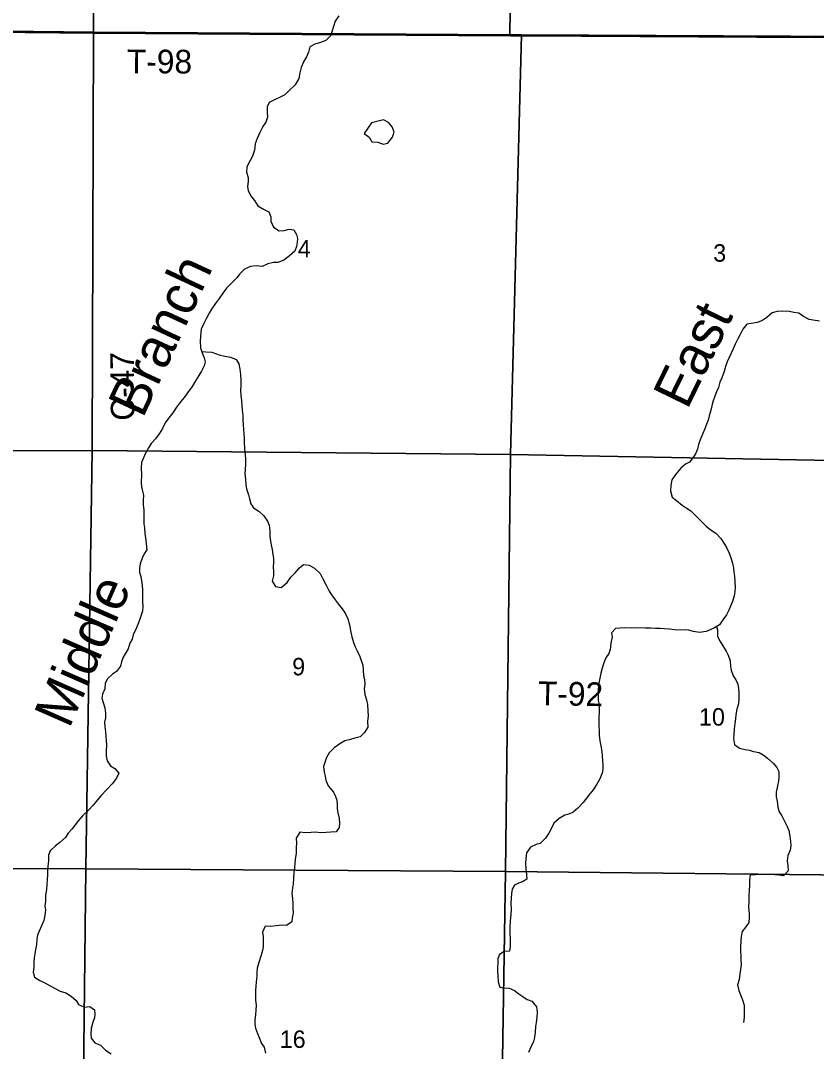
# Model space of a CAD drawing. Extents: x 1772825 to 1773716, y 1138558 to 1139032.
# Drawn here: x 1772825.891 to 1772826.846, y 1138559.911 to 1138561.147 of the extents above; entities that cross this region are included whole.
import ezdxf

# ---------------------------------------------------------------- set-up
doc = ezdxf.new("R2010")
doc.units = 0
for name, color, linetype in [('GM_X_County_Road_Text', 7, 'Continuous'), ('GM_X_Minor_Lake', 7, 'Continuous'), ('GM_X_Minor_River', 7, 'Continuous'), ('GM_X_Minor_River_Text', 7, 'Continuous'), ('GM_X_Section', 7, 'Continuous'), ('GM_X_Section_Text', 7, 'Continuous'), ('GM_X_Township', 7, 'Continuous'), ('GM_X_Township_Road_Text', 7, 'Continuous')]:
    doc.layers.add(name, color=color, linetype=linetype)

msp = doc.modelspace()

# ---------------------------------------------------------------- linework, layer by layer
at = {"layer": 'GM_X_Minor_Lake'}
for points in [[(1772826.3344, 1138561.0034), (1772826.3373, 1138561.0073), (1772826.3393, 1138561.0134), (1772826.3369, 1138561.0198), (1772826.3325, 1138561.0248), (1772826.3265, 1138561.028), (1772826.3121, 1138561.0244), (1772826.3036, 1138561.0115)], [(1772826.3036, 1138561.0115), (1772826.3095, 1138561.0073), (1772826.3127, 1138561.0018), (1772826.3199, 1138561.0014), (1772826.3261, 1138560.9988), (1772826.332, 1138561.0001), (1772826.3344, 1138561.0034)]]:
    msp.add_lwpolyline(points, dxfattribs=at)
at = {"layer": 'GM_X_Minor_River'}
for points in [[(1772826.273, 1138561.1527), (1772826.2686, 1138561.1465), (1772826.2667, 1138561.1398), (1772826.2646, 1138561.1337), (1772826.2629, 1138561.1286), (1772826.2576, 1138561.1231), (1772826.2512, 1138561.1209), (1772826.2444, 1138561.1188), (1772826.2384, 1138561.1157), (1772826.2365, 1138561.1093), (1772826.2342, 1138561.1034), (1772826.2308, 1138561.0977), (1772826.228, 1138561.0907), (1772826.2264, 1138561.0844), (1772826.2249, 1138561.0776), (1772826.2206, 1138561.0702), (1772826.214, 1138561.0638), (1772826.2081, 1138561.0581), (1772826.2028, 1138561.0551), (1772826.196, 1138561.052), (1772826.1894, 1138561.0488), (1772826.1871, 1138561.0437), (1772826.1871, 1138561.0374), (1772826.1875, 1138561.0313), (1772826.1854, 1138561.0251), (1772826.182, 1138561.02), (1772826.1784, 1138561.0128), (1772826.175, 1138561.0057), (1772826.1725, 1138560.9993), (1772826.1718, 1138560.9915), (1772826.1693, 1138560.9843), (1772826.1667, 1138560.9794), (1772826.1625, 1138560.9718), (1772826.1623, 1138560.9652), (1772826.1644, 1138560.9587), (1772826.1644, 1138560.954), (1772826.1635, 1138560.9479), (1772826.1644, 1138560.9428), (1772826.1682, 1138560.9358), (1772826.1718, 1138560.9311), (1772826.176, 1138560.925), (1772826.1826, 1138560.9208), (1772826.189, 1138560.9176), (1772826.1913, 1138560.9115), (1772826.1915, 1138560.9064), (1772826.1945, 1138560.8994), (1772826.2013, 1138560.895), (1772826.2075, 1138560.8951), (1772826.2136, 1138560.8968), (1772826.2189, 1138560.8962), (1772826.2223, 1138560.8903), (1772826.2234, 1138560.8856), (1772826.2232, 1138560.8808), (1772826.2223, 1138560.8761), (1772826.2202, 1138560.8706), (1772826.2138, 1138560.8651), (1772826.207, 1138560.8596), (1772826.2, 1138560.8568), (1772826.1945, 1138560.8568), (1772826.1879, 1138560.8554), (1772826.1812, 1138560.852), (1772826.1739, 1138560.8528), (1772826.1671, 1138560.852), (1772826.1597, 1138560.8488), (1772826.154, 1138560.8431), (1772826.1508, 1138560.8384), (1772826.1442, 1138560.8321), (1772826.1383, 1138560.8262), (1772826.134, 1138560.8203), (1772826.1296, 1138560.8137), (1772826.1249, 1138560.8073), (1772826.1205, 1138560.801), (1772826.1177, 1138560.7963), (1772826.1143, 1138560.79), (1772826.1113, 1138560.7839), (1772826.1081, 1138560.7771)], [(1772826.8497, 1138560.7867), (1772826.8418, 1138560.7877), (1772826.8371, 1138560.7885), (1772826.8302, 1138560.792), (1772826.8248, 1138560.796), (1772826.8189, 1138560.797), (1772826.8136, 1138560.798), (1772826.8047, 1138560.7984), (1772826.799, 1138560.7981), (1772826.7927, 1138560.7964), (1772826.7866, 1138560.7908), (1772826.7805, 1138560.787), (1772826.775, 1138560.785), (1772826.7676, 1138560.7839), (1772826.7626, 1138560.7828), (1772826.7578, 1138560.777), (1772826.7544, 1138560.7705), (1772826.7515, 1138560.7653), (1772826.7484, 1138560.7588), (1772826.7459, 1138560.7532), (1772826.7436, 1138560.7482), (1772826.7413, 1138560.7431), (1772826.739, 1138560.7378), (1772826.737, 1138560.732), (1772826.7353, 1138560.7263), (1772826.7324, 1138560.7184), (1772826.7302, 1138560.7134), (1772826.7283, 1138560.707), (1772826.726, 1138560.7019), (1772826.724, 1138560.6964), (1772826.7219, 1138560.6909), (1772826.7205, 1138560.6851), (1772826.7192, 1138560.6796), (1772826.7174, 1138560.6731), (1772826.7159, 1138560.6678), (1772826.7141, 1138560.6629), (1772826.712, 1138560.6572), (1772826.7091, 1138560.6508), (1772826.7064, 1138560.6442), (1772826.7046, 1138560.6387), (1772826.7033, 1138560.6332), (1772826.7008, 1138560.6274), (1772826.6975, 1138560.6225), (1772826.6937, 1138560.6176), (1772826.6889, 1138560.6149), (1772826.6832, 1138560.6102)], [(1772826.1081, 1138560.7771), (1772826.1071, 1138560.7684), (1772826.1069, 1138560.7625), (1772826.1073, 1138560.7547), (1772826.1094, 1138560.7472), (1772826.1115, 1138560.7424), (1772826.1126, 1138560.7377), (1772826.1115, 1138560.7328), (1772826.1084, 1138560.7267), (1772826.105, 1138560.7214), (1772826.1012, 1138560.7149), (1772826.0971, 1138560.7083), (1772826.0916, 1138560.7007), (1772826.0874, 1138560.6948), (1772826.0831, 1138560.6897), (1772826.0784, 1138560.6833), (1772826.074, 1138560.6764), (1772826.0691, 1138560.6706), (1772826.0647, 1138560.6645), (1772826.0615, 1138560.6579), (1772826.0577, 1138560.6512), (1772826.0532, 1138560.6452), (1772826.0479, 1138560.6399), (1772826.0447, 1138560.6347), (1772826.0411, 1138560.6281), (1772826.0386, 1138560.6228), (1772826.0364, 1138560.6169), (1772826.036, 1138560.6101), (1772826.0362, 1138560.6027), (1772826.0358, 1138560.5932), (1772826.0364, 1138560.5879), (1772826.0377, 1138560.5828), (1772826.0386, 1138560.5777), (1772826.0384, 1138560.5714), (1772826.0384, 1138560.5663), (1772826.039, 1138560.5602), (1772826.0392, 1138560.5546), (1772826.0392, 1138560.5485), (1772826.039, 1138560.5436), (1772826.0398, 1138560.5385), (1772826.0405, 1138560.5318), (1772826.0411, 1138560.5265), (1772826.0418, 1138560.5195), (1772826.0428, 1138560.5123), (1772826.0396, 1138560.5074), (1772826.0371, 1138560.5021), (1772826.0348, 1138560.4954), (1772826.0341, 1138560.4901), (1772826.0341, 1138560.4852), (1772826.0354, 1138560.4801), (1772826.0367, 1138560.4727), (1772826.0377, 1138560.4651), (1772826.0375, 1138560.4598), (1772826.0375, 1138560.4549), (1772826.0377, 1138560.4496), (1772826.0379, 1138560.4444), (1772826.0375, 1138560.4386), (1772826.035, 1138560.4314), (1772826.0329, 1138560.4245), (1772826.0299, 1138560.4177), (1772826.0263, 1138560.4101), (1772826.025, 1138560.4052), (1772826.0225, 1138560.4005), (1772826.0203, 1138560.3936), (1772826.0167, 1138560.3876), (1772826.014, 1138560.3826), (1772826.0123, 1138560.3779), (1772826.011, 1138560.3728), (1772826.0065, 1138560.3663), (1772826.0014, 1138560.3631), (1772825.9957, 1138560.3576), (1772825.9927, 1138560.3523), (1772825.9923, 1138560.3457), (1772825.9894, 1138560.3392), (1772825.9887, 1138560.3345), (1772825.9904, 1138560.3292), (1772825.9923, 1138560.3229), (1772825.993, 1138560.3165), (1772825.993, 1138560.3106), (1772825.9921, 1138560.3055), (1772825.9925, 1138560.3004), (1772825.9932, 1138560.2939), (1772825.9936, 1138560.2886), (1772825.9938, 1138560.2831), (1772825.9943, 1138560.278), (1772825.994, 1138560.2714), (1772825.9938, 1138560.2653), (1772825.9953, 1138560.259), (1772825.9991, 1138560.2532), (1772826.0042, 1138560.2499), (1772826.0091, 1138560.2445), (1772826.0064, 1138560.2384), (1772826.0012, 1138560.2317), (1772825.9942, 1138560.2242), (1772825.9881, 1138560.2175), (1772825.9834, 1138560.2124), (1772825.9785, 1138560.2058), (1772825.9726, 1138560.2001), (1772825.9656, 1138560.1933), (1772825.9607, 1138560.1874), (1772825.9569, 1138560.1823)], [(1772826.1086, 1138560.7501), (1772826.1135, 1138560.7498), (1772826.1209, 1138560.7494), (1772826.1296, 1138560.746), (1772826.1362, 1138560.7447), (1772826.1432, 1138560.7432), (1772826.1497, 1138560.7407), (1772826.1532, 1138560.7352), (1772826.1542, 1138560.729), (1772826.1551, 1138560.7225), (1772826.1555, 1138560.7159), (1772826.1555, 1138560.7091), (1772826.1551, 1138560.7038), (1772826.1555, 1138560.6973), (1772826.1563, 1138560.6913), (1772826.1566, 1138560.6856), (1772826.157, 1138560.6799), (1772826.1578, 1138560.6734), (1772826.158, 1138560.6681), (1772826.1583, 1138560.6621), (1772826.1587, 1138560.6566), (1772826.1589, 1138560.6516), (1772826.1593, 1138560.6463), (1772826.1595, 1138560.6412), (1772826.16, 1138560.6335), (1772826.1608, 1138560.6264), (1772826.161, 1138560.6209), (1772826.161, 1138560.6151), (1772826.1606, 1138560.6084), (1772826.1604, 1138560.6037), (1772826.161, 1138560.5967), (1772826.1616, 1138560.5906), (1772826.1623, 1138560.5853), (1772826.1646, 1138560.5781), (1772826.1657, 1138560.5734), (1772826.1676, 1138560.5673), (1772826.1706, 1138560.5626), (1772826.1771, 1138560.5588), (1772826.1831, 1138560.5529), (1772826.1876, 1138560.5468), (1772826.1895, 1138560.5417), (1772826.1901, 1138560.5353), (1772826.1901, 1138560.5286), (1772826.191, 1138560.5226), (1772826.192, 1138560.5177), (1772826.1929, 1138560.5127), (1772826.1939, 1138560.5068), (1772826.1948, 1138560.5021), (1772826.1948, 1138560.4974), (1772826.1944, 1138560.4915), (1772826.1948, 1138560.4868), (1772826.1946, 1138560.4809), (1772826.1931, 1138560.4748), (1772826.1971, 1138560.4684), (1772826.2037, 1138560.4672), (1772826.2109, 1138560.4729), (1772826.2156, 1138560.4794), (1772826.2205, 1138560.4845), (1772826.2258, 1138560.4906), (1772826.2308, 1138560.4947), (1772826.2376, 1138560.494), (1772826.2438, 1138560.4904), (1772826.2506, 1138560.4837), (1772826.2538, 1138560.4775), (1772826.2576, 1138560.4705), (1772826.2612, 1138560.4635), (1772826.2642, 1138560.4584), (1772826.2686, 1138560.4521), (1772826.2722, 1138560.4474), (1772826.2769, 1138560.4415), (1772826.2805, 1138560.4364), (1772826.2837, 1138560.4294), (1772826.286, 1138560.4223), (1772826.2871, 1138560.4155), (1772826.2886, 1138560.4079), (1772826.2907, 1138560.4011), (1772826.2926, 1138560.396), (1772826.2949, 1138560.3911), (1772826.2983, 1138560.3844), (1772826.302, 1138560.3738), (1772826.3022, 1138560.3681), (1772826.3028, 1138560.3613), (1772826.3037, 1138560.3566), (1772826.3041, 1138560.3511), (1772826.3035, 1138560.3454), (1772826.3041, 1138560.3388), (1772826.3062, 1138560.3325), (1772826.3073, 1138560.3268), (1772826.3079, 1138560.3192), (1772826.3083, 1138560.313), (1772826.3075, 1138560.3064), (1772826.3077, 1138560.2997), (1772826.3039, 1138560.2933), (1772826.2986, 1138560.2878), (1772826.2922, 1138560.2863), (1772826.2871, 1138560.2849), (1772826.2801, 1138560.283), (1772826.2742, 1138560.2796), (1772826.2676, 1138560.2749), (1772826.2616, 1138560.2688), (1772826.2583, 1138560.2631)], [(1772826.6832, 1138560.6102), (1772826.6772, 1138560.6031), (1772826.6726, 1138560.5963), (1772826.6711, 1138560.5896), (1772826.6708, 1138560.583), (1772826.6729, 1138560.5756), (1772826.678, 1138560.5714), (1772826.6849, 1138560.566), (1772826.6898, 1138560.5626), (1772826.6951, 1138560.5589), (1772826.7, 1138560.5543), (1772826.7074, 1138560.5471), (1772826.7136, 1138560.5408), (1772826.7185, 1138560.5368), (1772826.7253, 1138560.5323), (1772826.7311, 1138560.5258), (1772826.7358, 1138560.519), (1772826.7384, 1138560.5142), (1772826.7412, 1138560.5081), (1772826.7436, 1138560.5015), (1772826.7453, 1138560.4963), (1772826.7466, 1138560.4908), (1772826.7469, 1138560.4853), (1772826.7477, 1138560.4806), (1772826.7482, 1138560.4734), (1772826.7485, 1138560.4675), (1772826.7481, 1138560.4618), (1772826.7471, 1138560.4569), (1772826.7453, 1138560.4501), (1772826.743, 1138560.4448), (1772826.7407, 1138560.4399), (1772826.738, 1138560.4344), (1772826.7338, 1138560.4281), (1772826.7296, 1138560.4223), (1772826.7237, 1138560.4187), (1772826.7185, 1138560.4163), (1772826.7136, 1138560.4141), (1772826.7058, 1138560.4132), (1772826.6986, 1138560.4144), (1772826.6923, 1138560.4159), (1772826.6876, 1138560.4162), (1772826.6827, 1138560.416), (1772826.6756, 1138560.4163), (1772826.6696, 1138560.4171), (1772826.6635, 1138560.4173), (1772826.6584, 1138560.4177), (1772826.6527, 1138560.4179), (1772826.6474, 1138560.4182), (1772826.6408, 1138560.4184), (1772826.629, 1138560.4185), (1772826.6239, 1138560.4183), (1772826.6159, 1138560.4186), (1772826.6104, 1138560.4181), (1772826.6049, 1138560.4179), (1772826.6001, 1138560.4128), (1772826.601, 1138560.4077), (1772826.5993, 1138560.4005), (1772826.5986, 1138560.3927), (1772826.5969, 1138560.3878), (1772826.5934, 1138560.3827), (1772826.5909, 1138560.3769), (1772826.5888, 1138560.3702), (1772826.5872, 1138560.3642), (1772826.586, 1138560.3583), (1772826.585, 1138560.3524), (1772826.584, 1138560.3447), (1772826.584, 1138560.3386), (1772826.5841, 1138560.332), (1772826.5852, 1138560.3255), (1772826.5854, 1138560.3175), (1772826.5851, 1138560.3111), (1772826.5849, 1138560.3063), (1772826.585, 1138560.3008), (1772826.5852, 1138560.2953), (1772826.5853, 1138560.2898), (1772826.5861, 1138560.2832), (1772826.5879, 1138560.2752), (1772826.5884, 1138560.2699), (1772826.589, 1138560.2652), (1772826.5893, 1138560.2595), (1772826.5898, 1138560.254), (1772826.5898, 1138560.2492), (1772826.5888, 1138560.2443), (1772826.5857, 1138560.2367), (1772826.5824, 1138560.2311), (1772826.5782, 1138560.2245), (1772826.5742, 1138560.2195), (1772826.57, 1138560.2143), (1772826.5663, 1138560.2092), (1772826.5598, 1138560.2022), (1772826.5541, 1138560.1977), (1772826.549, 1138560.1953), (1772826.544, 1138560.1938), (1772826.5375, 1138560.19), (1772826.5309, 1138560.1844), (1772826.5278, 1138560.1774), (1772826.5251, 1138560.1725), (1772826.5211, 1138560.1663), (1772826.5146, 1138560.1601), (1772826.5096, 1138560.159), (1772826.5028, 1138560.1556)], [(1772826.7261, 1138560.4202), (1772826.7273, 1138560.4157), (1772826.7272, 1138560.4081), (1772826.7306, 1138560.4024), (1772826.7338, 1138560.3972), (1772826.7375, 1138560.3907), (1772826.7399, 1138560.386), (1772826.7423, 1138560.379), (1772826.7429, 1138560.3727), (1772826.7436, 1138560.3678), (1772826.7462, 1138560.3613), (1772826.7494, 1138560.3563), (1772826.7518, 1138560.3512), (1772826.7525, 1138560.3461), (1772826.7527, 1138560.3409), (1772826.7528, 1138560.3345), (1772826.7524, 1138560.3277), (1772826.7506, 1138560.321), (1772826.7491, 1138560.3144), (1772826.7487, 1138560.3097), (1772826.7479, 1138560.304), (1772826.7472, 1138560.2974), (1772826.7468, 1138560.2909), (1772826.7464, 1138560.286), (1772826.7477, 1138560.2789), (1772826.7535, 1138560.2742), (1772826.7603, 1138560.2728), (1772826.7655, 1138560.2718), (1772826.7706, 1138560.2702), (1772826.7772, 1138560.2691), (1772826.7821, 1138560.2664), (1772826.7872, 1138560.2625), (1772826.7942, 1138560.2564), (1772826.7983, 1138560.2511), (1772826.8007, 1138560.2463), (1772826.8007, 1138560.2399), (1772826.8003, 1138560.2347), (1772826.7991, 1138560.2291), (1772826.7977, 1138560.2217), (1772826.7977, 1138560.216), (1772826.7988, 1138560.2108), (1772826.7997, 1138560.2034), (1772826.8011, 1138560.1981), (1772826.8045, 1138560.1932), (1772826.8075, 1138560.1869), (1772826.8107, 1138560.1802), (1772826.8129, 1138560.1755), (1772826.8142, 1138560.1688), (1772826.8149, 1138560.1625), (1772826.8151, 1138560.1578), (1772826.8143, 1138560.1521), (1772826.8118, 1138560.1457), (1772826.811, 1138560.1392), (1772826.8117, 1138560.1335), (1772826.8122, 1138560.1273), (1772826.8066, 1138560.1214), (1772826.801, 1138560.1221), (1772826.796, 1138560.1225), (1772826.79, 1138560.1227), (1772826.7837, 1138560.1228), (1772826.7786, 1138560.1228), (1772826.7729, 1138560.1226), (1772826.7664, 1138560.1225), (1772826.7658, 1138560.1161), (1772826.7658, 1138560.1094), (1772826.7652, 1138560.1039), (1772826.7649, 1138560.0975), (1772826.7649, 1138560.0906), (1772826.7646, 1138560.0838), (1772826.7651, 1138560.076), (1772826.7653, 1138560.0711), (1772826.7649, 1138560.0654), (1772826.7614, 1138560.0601), (1772826.7568, 1138560.0543), (1772826.7556, 1138560.0484), (1772826.7552, 1138560.0433), (1772826.7548, 1138560.0357), (1772826.7548, 1138560.0306), (1772826.7551, 1138560.0258), (1772826.7552, 1138560.0207), (1772826.7556, 1138560.0148), (1772826.755, 1138560.0088), (1772826.7542, 1138560.0038), (1772826.7532, 1138559.997), (1772826.7514, 1138559.9904), (1772826.7527, 1138559.9835), (1772826.7549, 1138559.9786), (1772826.7574, 1138559.9723), (1772826.7592, 1138559.9659), (1772826.7592, 1138559.9586), (1772826.7591, 1138559.9514), (1772826.7583, 1138559.9454)], [(1772826.2583, 1138560.2631), (1772826.2561, 1138560.2572), (1772826.2546, 1138560.2523), (1772826.2553, 1138560.2457), (1772826.2565, 1138560.2407), (1772826.2576, 1138560.2358), (1772826.2604, 1138560.2292), (1772826.2667, 1138560.2216), (1772826.2691, 1138560.2165), (1772826.2706, 1138560.2118), (1772826.2712, 1138560.2068), (1772826.271, 1138560.2019), (1772826.2718, 1138560.1968), (1772826.2735, 1138560.1901), (1772826.274, 1138560.1843), (1772826.2735, 1138560.1793), (1772826.2699, 1138560.174), (1772826.2633, 1138560.1735), (1772826.2578, 1138560.1731), (1772826.251, 1138560.1729), (1772826.2449, 1138560.1735), (1772826.24, 1138560.1731), (1772826.2332, 1138560.1729), (1772826.2264, 1138560.1734), (1772826.2218, 1138560.1666), (1772826.2222, 1138560.1606), (1772826.222, 1138560.1554), (1772826.2217, 1138560.1484), (1772826.2205, 1138560.141), (1772826.2201, 1138560.1363), (1772826.2198, 1138560.131), (1772826.219, 1138560.1255), (1772826.2186, 1138560.1181), (1772826.2181, 1138560.1116), (1772826.2175, 1138560.1069), (1772826.2167, 1138560.1005), (1772826.2175, 1138560.0936), (1772826.2179, 1138560.0889), (1772826.2179, 1138560.0824), (1772826.2181, 1138560.0766), (1772826.2171, 1138560.0709), (1772826.2167, 1138560.066), (1772826.2101, 1138560.0616), (1772826.2052, 1138560.062), (1772826.1978, 1138560.0614), (1772826.1912, 1138560.0604), (1772826.1846, 1138560.061), (1772826.1814, 1138560.0536), (1772826.1821, 1138560.0483), (1772826.1823, 1138560.0415), (1772826.1821, 1138560.0362), (1772826.1812, 1138560.0299), (1772826.1789, 1138560.0235), (1772826.1772, 1138560.0172), (1772826.1751, 1138560.0104), (1772826.1748, 1138560.0055), (1772826.1746, 1138560.0003), (1772826.1738, 1138559.9939), (1772826.1734, 1138559.9886), (1772826.1731, 1138559.9839), (1772826.1731, 1138559.9776), (1772826.1732, 1138559.9721), (1772826.1738, 1138559.966), (1772826.1734, 1138559.96), (1772826.1729, 1138559.9545), (1772826.1723, 1138559.9486), (1772826.1723, 1138559.9433), (1772826.1729, 1138559.9385), (1772826.1755, 1138559.9323), (1772826.1774, 1138559.9274), (1772826.1804, 1138559.9203), (1772826.1835, 1138559.9156), (1772826.1852, 1138559.9086)], [(1772825.9569, 1138560.1823), (1772825.9527, 1138560.1771), (1772825.9482, 1138560.1724), (1772825.945, 1138560.1671), (1772825.9384, 1138560.1612), (1772825.9331, 1138560.1574), (1772825.9268, 1138560.1512), (1772825.9249, 1138560.1462), (1772825.9249, 1138560.1394), (1772825.924, 1138560.133), (1772825.9234, 1138560.1276), (1772825.9234, 1138560.1222), (1772825.9232, 1138560.1167), (1772825.9227, 1138560.1104), (1772825.9223, 1138560.1049), (1772825.9213, 1138560.0979), (1772825.9212, 1138560.0905), (1772825.9204, 1138560.0854), (1772825.9212, 1138560.0803), (1772825.9202, 1138560.0736), (1772825.9191, 1138560.0676), (1772825.9164, 1138560.0613), (1772825.9134, 1138560.0548), (1772825.9117, 1138560.0499), (1772825.9109, 1138560.0452), (1772825.9102, 1138560.0387), (1772825.9092, 1138560.033), (1772825.9083, 1138560.0277), (1772825.9075, 1138560.0228), (1772825.907, 1138560.0167), (1772825.9072, 1138560.0118), (1772825.9062, 1138560.0056), (1772825.9079, 1138559.9997), (1772825.9142, 1138559.9957), (1772825.9202, 1138559.9927), (1772825.9268, 1138559.9894), (1772825.9336, 1138559.9855), (1772825.9389, 1138559.983), (1772825.9456, 1138559.9809), (1772825.952, 1138559.9768), (1772825.958, 1138559.9715), (1772825.9607, 1138559.9667), (1772825.9681, 1138559.9635), (1772825.9743, 1138559.9644), (1772825.98, 1138559.9603), (1772825.9805, 1138559.9555), (1772825.9798, 1138559.9508), (1772825.9781, 1138559.9455), (1772825.9758, 1138559.9381), (1772825.9754, 1138559.9315), (1772825.976, 1138559.9267), (1772825.9802, 1138559.9208), (1772825.9872, 1138559.9182), (1772825.9932, 1138559.9121), (1772825.9998, 1138559.9076)], [(1772826.5028, 1138560.1556), (1772826.4982, 1138560.1488), (1772826.4973, 1138560.1418), (1772826.4969, 1138560.1368), (1772826.4974, 1138560.1298), (1772826.4983, 1138560.123), (1772826.4987, 1138560.1173), (1772826.4933, 1138560.1139), (1772826.4886, 1138560.1124), (1772826.4838, 1138560.1102), (1772826.4811, 1138560.1051), (1772826.4802, 1138560.1), (1772826.4797, 1138560.0945), (1772826.4795, 1138560.0884), (1772826.4796, 1138560.0812), (1772826.4792, 1138560.0751), (1772826.4786, 1138560.067), (1772826.4783, 1138560.0598), (1772826.4781, 1138560.052), (1772826.4784, 1138560.0465), (1772826.4784, 1138560.0366), (1772826.4777, 1138560.0309), (1772826.4715, 1138560.0304), (1772826.4656, 1138560.0267), (1772826.4638, 1138560.0216), (1772826.4636, 1138560.0168), (1772826.4632, 1138560.0113), (1772826.4633, 1138560.0064), (1772826.4639, 1138560.0011), (1772826.4642, 1138559.9939), (1772826.466, 1138559.9878), (1772826.4708, 1138559.987), (1772826.4774, 1138559.9866), (1772826.4839, 1138559.9835), (1772826.4889, 1138559.9798), (1772826.4939, 1138559.9766), (1772826.4988, 1138559.9729), (1772826.5046, 1138559.9708), (1772826.5101, 1138559.9641), (1772826.511, 1138559.9578), (1772826.5106, 1138559.9514), (1772826.5096, 1138559.9453), (1772826.509, 1138559.9406), (1772826.5085, 1138559.9336), (1772826.5079, 1138559.9273), (1772826.5067, 1138559.9224), (1772826.5035, 1138559.9156), (1772826.5004, 1138559.9092)]]:
    msp.add_lwpolyline(points, dxfattribs=at)
at = {"layer": 'GM_X_Section'}
for points in [[(1772825.4805, 1138561.6434), (1772825.9823, 1138561.6329), (1772825.9788, 1138561.1333), (1772825.4749, 1138561.1387)], [(1772825.9823, 1138561.6329), (1772826.4849, 1138561.6314), (1772826.4783, 1138561.1299), (1772825.9788, 1138561.1333)], [(1772826.4849, 1138561.6314), (1772826.9813, 1138561.6303), (1772826.9799, 1138561.1276), (1772826.9762, 1138561.1277), (1772826.4923, 1138561.13), (1772826.4783, 1138561.1299)], [(1772825.473, 1138561.1387), (1772825.4749, 1138561.1387), (1772825.9788, 1138561.1333), (1772825.9771, 1138560.6314), (1772825.4699, 1138560.6299)], [(1772826.4923, 1138561.13), (1772826.4788, 1138560.6265), (1772825.9771, 1138560.6314), (1772825.9788, 1138561.1333), (1772826.4783, 1138561.1299)], [(1772826.4923, 1138561.13), (1772826.9762, 1138561.1277), (1772826.9725, 1138560.6175), (1772826.4788, 1138560.6265)], [(1772825.4699, 1138560.6299), (1772825.9771, 1138560.6314), (1772825.9696, 1138560.1298), (1772825.4647, 1138560.1309)], [(1772825.9771, 1138560.6314), (1772826.4788, 1138560.6265), (1772826.4728, 1138560.1264), (1772825.9696, 1138560.1298)], [(1772826.4788, 1138560.6265), (1772826.9725, 1138560.6175), (1772826.9648, 1138560.1213), (1772826.4728, 1138560.1264)], [(1772825.4647, 1138560.1309), (1772825.9696, 1138560.1298), (1772825.964, 1138559.63), (1772825.4596, 1138559.6311)], [(1772825.9696, 1138560.1298), (1772826.4728, 1138560.1264), (1772826.4648, 1138559.6249), (1772825.964, 1138559.63)], [(1772826.9648, 1138560.1213), (1772826.9674, 1138559.6213), (1772826.4648, 1138559.6249), (1772826.4728, 1138560.1264)]]:
    msp.add_lwpolyline(points, close=True, dxfattribs=at)
at = {"layer": 'GM_X_Township'}
for points in [[(1772825.3579, 1138561.138), (1772825.4728, 1138561.1365), (1772825.8143, 1138561.1337), (1772825.9786, 1138561.1321), (1772826.4791, 1138561.1287), (1772826.4941, 1138561.1288), (1772826.8442, 1138561.1267), (1772827.2975, 1138561.1277), (1772827.5133, 1138561.1311), (1772827.9826, 1138561.1355), (1772827.9839, 1138561.2587)], [(1772827.2975, 1138561.1277), (1772826.8442, 1138561.1267), (1772826.4941, 1138561.1288), (1772826.4791, 1138561.1287), (1772825.9786, 1138561.1321), (1772825.8143, 1138561.1337), (1772825.4728, 1138561.1365), (1772825.3579, 1138561.138)]]:
    msp.add_lwpolyline(points, dxfattribs=at)

# ---------------------------------------------------------------- texts
at = {"layer": 'GM_X_County_Road_Text'}
msp.add_text('C-47', height=0.02841, rotation=90.6782, dxfattribs=at).set_placement((1772826.0281, 1138560.6673))
at = {"layer": 'GM_X_Minor_River_Text'}
for s, height, rotation, p in [('Branch', 0.04736, 65.0337, (1772826.0378, 1138560.669)), ('East', 0.04737, 63.9699, (1772826.6909, 1138560.6793)), ('Middle', 0.04736, 66.2929, (1772825.9496, 1138560.2968))]:
    msp.add_text(s, height=height, rotation=rotation, dxfattribs=at).set_placement(p)
at = {"layer": 'GM_X_Section_Text'}
for s, height, p in [('4', 0.0209, (1772826.2238, 1138560.8631)), ('3', 0.0209, (1772826.7221, 1138560.8579)), ('9', 0.0209, (1772826.2171, 1138560.3617)), ('10', 0.02093, (1772826.705, 1138560.3014)), ('16', 0.02093, (1772826.2021, 1138559.9148))]:
    msp.add_text(s, height=height, rotation=0, dxfattribs=at).set_placement(p)
at = {"layer": 'GM_X_Township_Road_Text'}
for s, rotation, p in [('T-98', 359.6511, (1772826.0188, 1138561.084)), ('T-92', 358.9438, (1772826.5117, 1138560.3261))]:
    msp.add_text(s, height=0.02841, rotation=rotation, dxfattribs=at).set_placement(p)

doc.saveas('drawing.dxf')
